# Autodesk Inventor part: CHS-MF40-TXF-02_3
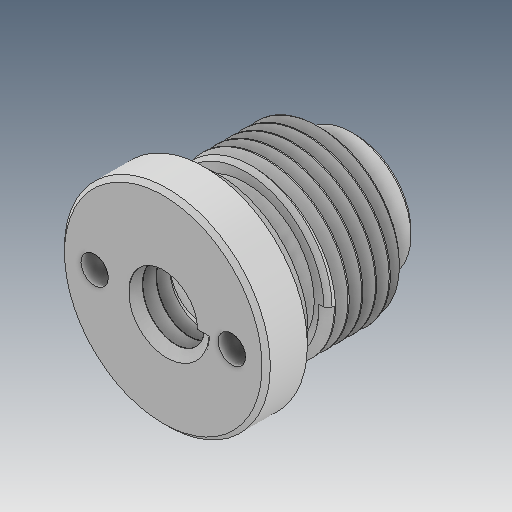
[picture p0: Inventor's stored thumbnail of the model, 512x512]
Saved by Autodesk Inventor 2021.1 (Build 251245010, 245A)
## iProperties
Created: 2019-04
Part Number: CHS-MF40-TXF-02_3
Material: Ogólny
Document SubType Name: Modeling
Designer: user
Density: 1 g/cm^3
Appearance: Domyślna
Author: user
Revision Number: ÈÎºÎ
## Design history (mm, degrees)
feature "ÊäÈë1"
node "Bryła1"
